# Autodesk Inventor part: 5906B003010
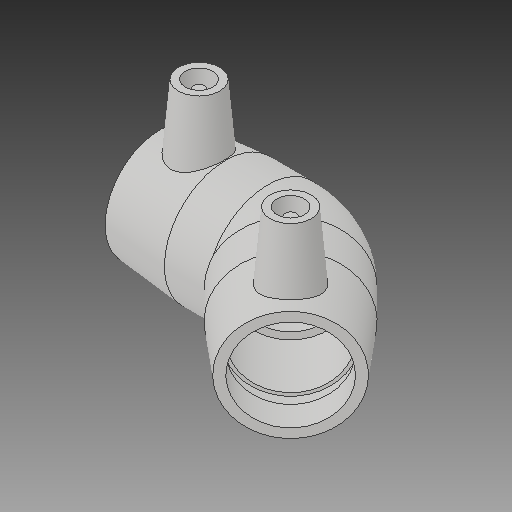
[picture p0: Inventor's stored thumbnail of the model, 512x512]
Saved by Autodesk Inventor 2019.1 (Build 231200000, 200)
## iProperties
Created: 2017-06
Part Number: 5906B003010
Material: Generic
Description: PLASSON 45° ELBOW 1''
Document SubType Name: Modeling
Designer: KIM
Mass: 55.0731 g
Surface Area: 148.067 cm^2
Volume: 55.0731 cm^3
Density: 1 g/cm^3
Appearance: Default
Author: KIM
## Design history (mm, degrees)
derived "5906B.ipt"
feature "Solid1::5906B.ipt"
tag "TaggingFeature1"
body "Solid1"
other parameters: "d2" = 44.45, "d4" = 23.749, "d5" = 40.005, "d8" = 168 deg, "d10" = 15.6464, "d11" = 5.21547, "d14" = 17.6296, "d18" = 33.3, "d19" = 3.52592, "d20" = 168 deg, "d22" = 40.894, "d23" = 44.45, "d24" = 39.66718, "d29" = 42.926, "d30" = 15, "d31" = 33.2486, "d34" = 5 deg, "d35" = 12, "d39" = 0, "d41" = 4, "d42" = 14, "d43" = 0, "d44" = 9.6, "d45" = 4.8, "d46" = 6, "d47" = 0, "d49" = 33.3, "d50" = 28.305, "d51" = 15.6464, "d52" = 39.116, "d54" = 135 deg, "d65" = 33.3, "d67" = 45 deg, "d71" = 135 deg, "d75" = 2.2225, "d82" = 45 deg, "d83" = 39.116, "d84" = 40.005, "d86" = 20.0025, "d87" = 135 deg, "d88" = 94.996, "d90" = 39.116, "d91" = 0, "d92" = 39.116, "d93" = 0, "d94" = 135 deg, "d95" = 19.83359, "d98" = 94.996, "d99" = 28.4988, "d101" = 3, "d102" = 0, "d103" = 3, "d104" = 0, "d105" = 11.34364, "d106" = 2.83591, "d_" = 33.3, "L_" = 94.996, "L_1" = 39.116, "D_" = 44.45, "A_" = 42.926, "d_2" = 12
